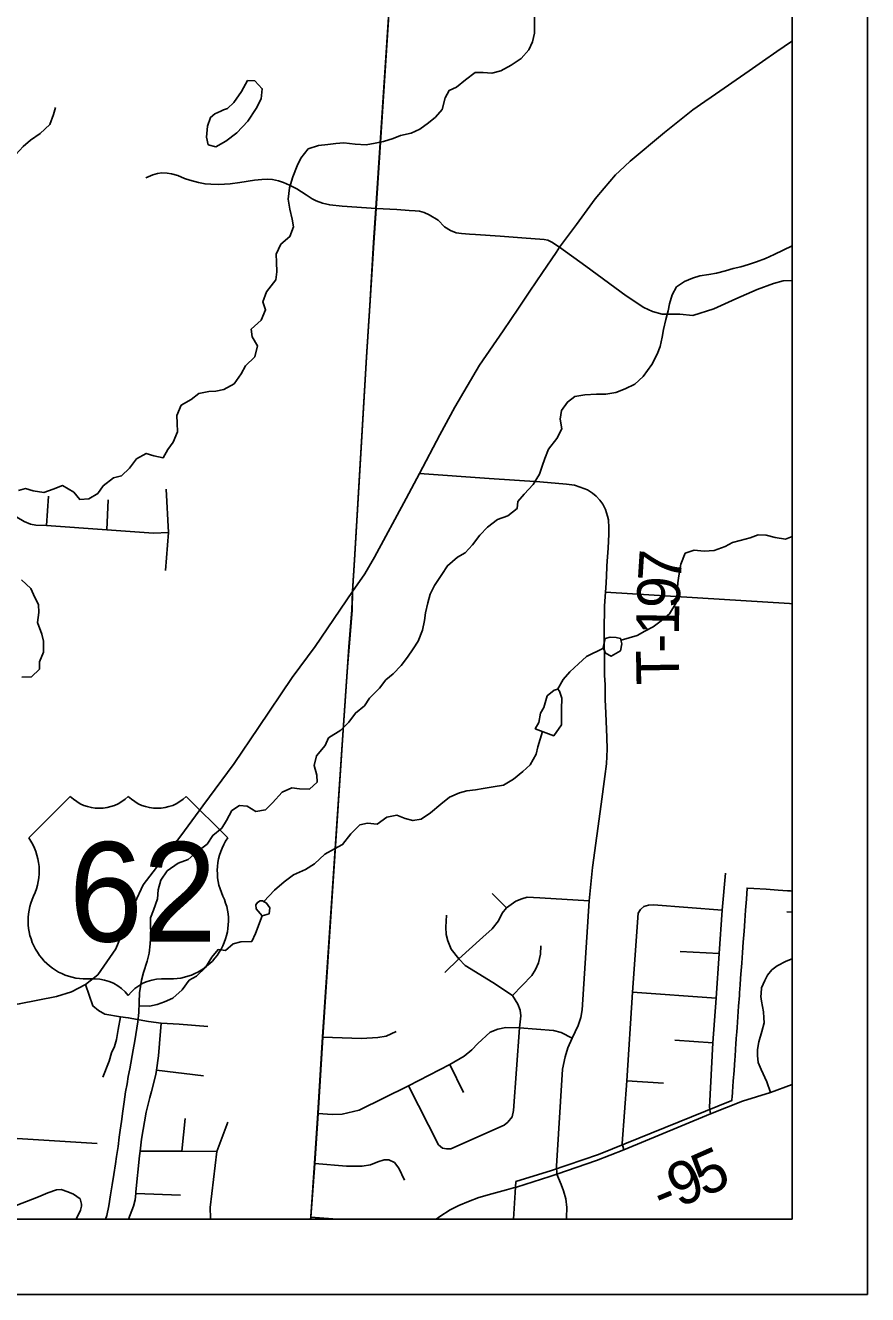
# Model space of a CAD drawing. Extents: x 0 to 34, y 0 to 22.
# Drawn here: x 7.884 to 9, y 14 to 15.681 of the extents above; entities that cross this region are included whole.
import ezdxf

# ---------------------------------------------------------------- set-up
doc = ezdxf.new("R2010")
doc.units = 0
for name, color, linetype in [('GM_X_City_Street', 7, 'Continuous'), ('GM_X_Corporation', 7, 'Continuous'), ('GM_X_County_Road', 7, 'Continuous'), ('GM_X_County_Road_Text', 7, 'Continuous'), ('GM_X_Minor_Lake', 7, 'Continuous'), ('GM_X_Minor_River', 7, 'Continuous'), ('GM_X_Township_Road', 7, 'Continuous'), ('GM_X_Township_Road_Text', 7, 'Continuous'), ('GM_X_US_Location', 7, 'Continuous'), ('GM_X_US_Route', 7, 'Continuous'), ('GM_X_US_Shield', 7, 'Continuous'), ('SH_Data', 7, 'Continuous')]:
    doc.layers.add(name, color=color, linetype=linetype)

msp = doc.modelspace()

# ---------------------------------------------------------------- linework, layer by layer
at = {"layer": 'GM_X_City_Street'}
for p, q in [((7.9123, 15.0186), (7.9148, 15.0576)), ((7.9922, 15.013), (7.994, 15.0525)), ((8.5026, 14.5312), (8.5215, 14.5123)), ((8.4398, 14.4266), (8.4584, 14.4448)), ((8.7518, 14.4545), (8.8034, 14.4519)), ((8.6883, 14.4006), (8.7994, 14.3925)), ((8.7445, 14.3368), (8.7951, 14.3337)), ((8.0579, 14.2972), (8.12, 14.2897)), ((8.4647, 14.2675), (8.4465, 14.3047)), ((8.681, 14.2831), (8.7295, 14.28)), ((8.0916, 14.19), (8.0957, 14.2332)), ((8.1376, 14.1897), (8.1524, 14.2283)), ((8.0303, 14.1339), (8.0896, 14.1318)), ((8.2625, 14.1028), (8.2971, 14.1))]:
    msp.add_line(p, q, dxfattribs=at)
for points in [[(8.3274, 15.0917), (8.3363, 15.2416), (8.3407, 15.3098), (8.3456, 15.3931), (8.3487, 15.4386), (8.3661, 15.702)], [(8.0437, 15.4792), (8.0531, 15.4833), (8.0593, 15.485), (8.0649, 15.4858), (8.0718, 15.4855), (8.0777, 15.4846), (8.086, 15.4822), (8.0949, 15.4782), (8.1019, 15.476), (8.1135, 15.4729), (8.1222, 15.4712), (8.1299, 15.4707), (8.1404, 15.4703), (8.1554, 15.4714), (8.1682, 15.473), (8.1875, 15.476), (8.1974, 15.4771), (8.2044, 15.4774), (8.2114, 15.477), (8.2193, 15.4753), (8.2263, 15.473), (8.2341, 15.4696), (8.2436, 15.4645), (8.256, 15.4565), (8.264, 15.4514), (8.2692, 15.4486), (8.2778, 15.4457), (8.2874, 15.4434), (8.3039, 15.4415), (8.3487, 15.4386)], [(8.3487, 15.4386), (8.3762, 15.4371), (8.3926, 15.436), (8.4006, 15.4356), (8.4064, 15.4349), (8.4126, 15.4334), (8.419, 15.4303), (8.4309, 15.423), (8.4393, 15.4145), (8.4473, 15.4093), (8.4547, 15.4065), (8.4619, 15.4054), (8.4725, 15.4044), (8.4805, 15.404), (8.5132, 15.4017), (8.5476, 15.3993), (8.5658, 15.398), (8.5713, 15.3976), (8.5763, 15.3966), (8.5818, 15.3941), (8.592, 15.3872)], [(8.592, 15.3872), (8.6267, 15.362), (8.6799, 15.323), (8.7036, 15.3073), (8.715, 15.3023), (8.7276, 15.2987), (8.7511, 15.2985), (8.7684, 15.2969), (8.7962, 15.3057), (8.8252, 15.3187), (8.8535, 15.3312), (8.8754, 15.3394), (8.8879, 15.3427), (8.9, 15.3431)], [(8.3176, 14.9313), (8.3203, 14.9727), (8.3274, 15.0917)], [(7.7149, 15.0649), (7.8018, 15.0588), (7.8254, 15.0572), (7.8335, 15.0558), (7.84, 15.0528), (7.8479, 15.0482), (7.8728, 15.0297), (7.8825, 15.0239), (7.8911, 15.0204), (7.8982, 15.0192), (7.9123, 15.0186), (7.9922, 15.013), (8.0541, 15.0084), (8.0738, 15.0093)], [(8.0698, 14.959), (8.0738, 15.0093), (8.0708, 15.067)], [(8.2623, 14.1), (8.2625, 14.1028), (8.2675, 14.1737), (8.2719, 14.2398), (8.2782, 14.341), (8.3054, 14.7474), (8.311, 14.8311), (8.313, 14.8575), (8.317, 14.9065), (8.3176, 14.9313)], [(8.6529, 14.9305), (8.8965, 14.9154), (8.9, 14.9151)], [(8.7917, 14.2395), (8.7907, 14.2482), (8.7951, 14.3337), (8.7994, 14.3925), (8.8034, 14.4519), (8.8075, 14.5093), (8.8116, 14.5583)], [(8.4584, 14.4448), (8.4903, 14.4736), (8.5026, 14.4843), (8.5109, 14.4949), (8.516, 14.5052), (8.5215, 14.5123), (8.5338, 14.521), (8.542, 14.5241), (8.5491, 14.5265), (8.5657, 14.5257), (8.6313, 14.5214)], [(8.677, 14.1916), (8.6749, 14.2003), (8.681, 14.2831), (8.6883, 14.4006), (8.696, 14.5054), (8.6993, 14.5101), (8.7035, 14.5141), (8.7098, 14.516), (8.7165, 14.5164), (8.8075, 14.5093)], [(8.3916, 14.2767), (8.4315, 14.1985), (8.4366, 14.1941), (8.4422, 14.1933), (8.4477, 14.1929), (8.5184, 14.2245), (8.5235, 14.2285), (8.529, 14.2356), (8.531, 14.2439), (8.5389, 14.3532), (8.5405, 14.3694), (8.5397, 14.3769), (8.5365, 14.3848), (8.5294, 14.3962), (8.5034, 14.4132), (8.467, 14.4357), (8.4584, 14.4448), (8.4481, 14.4574), (8.4438, 14.4685), (8.4418, 14.4771), (8.4414, 14.4866), (8.4422, 14.5024)], [(8.5294, 14.3962), (8.5551, 14.4227), (8.5602, 14.4306), (8.5641, 14.4393), (8.5665, 14.4511), (8.5669, 14.4618)], [(7.9636, 14.4109), (7.9736, 14.3823), (7.9811, 14.3761), (7.9893, 14.3714), (8.0104, 14.3678), (8.0204, 14.3668), (8.0472, 14.3619), (8.0641, 14.3597), (8.0881, 14.3583), (8.1259, 14.3552)], [(7.9866, 14.2881), (7.9952, 14.3092), (7.9981, 14.3202), (8.0024, 14.3288), (8.0051, 14.3379), (8.0069, 14.3511), (8.0104, 14.3678)], [(8.0209, 14.1), (8.0272, 14.1171), (8.0296, 14.1254), (8.0303, 14.1339), (8.0305, 14.136), (8.0354, 14.1837), (8.0362, 14.1902), (8.038, 14.206), (8.0442, 14.2415), (8.0491, 14.2612), (8.0511, 14.2691), (8.0571, 14.2917), (8.0579, 14.2972), (8.0605, 14.3163), (8.0619, 14.3326), (8.0641, 14.3597)], [(8.2719, 14.2398), (8.2908, 14.2386), (8.304, 14.2392), (8.3264, 14.2445), (8.3916, 14.2767), (8.4465, 14.3047), (8.4655, 14.3157), (8.4757, 14.3244), (8.4836, 14.3327), (8.4998, 14.3477), (8.5101, 14.3516), (8.5207, 14.3536), (8.5389, 14.3532), (8.5839, 14.3497), (8.5938, 14.3473), (8.6084, 14.3398)], [(8.2782, 14.341), (8.3293, 14.3394), (8.3513, 14.3406), (8.3623, 14.3425), (8.3756, 14.3485)], [(7.8315, 14.2092), (7.8735, 14.2066), (7.9792, 14.2)], [(8.0362, 14.1902), (8.0916, 14.19), (8.1376, 14.1897)], [(8.1294, 14.1), (8.1294, 14.1012), (8.1291, 14.1152), (8.1376, 14.1897)], [(8.2675, 14.1737), (8.3097, 14.1702), (8.3305, 14.1702), (8.3412, 14.1718), (8.351, 14.1759), (8.3595, 14.1787), (8.3658, 14.1784), (8.3731, 14.1749), (8.379, 14.1677), (8.3866, 14.1516)], [(7.6779, 14.1245), (7.7474, 14.1256), (7.7764, 14.1231), (7.8273, 14.1152), (7.8366, 14.1138), (7.8536, 14.1144), (7.8699, 14.1169), (7.8743, 14.1187), (7.8855, 14.1235), (7.9015, 14.1294), (7.914, 14.135), (7.9254, 14.1387), (7.9315, 14.1394), (7.9402, 14.1363), (7.9481, 14.1332), (7.9568, 14.1267)], [(7.9515, 14.1), (7.9515, 14.1), (7.9574, 14.1117), (7.9586, 14.117), (7.9583, 14.1196), (7.9568, 14.1267)]]:
    msp.add_lwpolyline(points, dxfattribs=at)
at = {"layer": 'GM_X_Corporation'}
msp.add_lwpolyline([(6.2393, 14.1), (8.5308, 14.1), (8.5331, 14.1354), (8.534, 14.1497), (8.5814, 14.1642), (8.6433, 14.1855), (8.8201, 14.257), (8.8202, 14.2591), (8.8204, 14.2611), (8.8209, 14.2686), (8.8219, 14.2827), (8.823, 14.297), (8.824, 14.3114), (8.8243, 14.3151), (8.825, 14.3255), (8.8255, 14.3319), (8.826, 14.3393), (8.8267, 14.3482), (8.8271, 14.3539), (8.8276, 14.3609), (8.8281, 14.368), (8.8291, 14.3819), (8.8301, 14.396), (8.8304, 14.3997), (8.8312, 14.4105), (8.8318, 14.4187), (8.8322, 14.4246), (8.8329, 14.4343), (8.8332, 14.4389), (8.8342, 14.4531), (8.8352, 14.467), (8.8363, 14.4813), (8.8373, 14.4951), (8.8383, 14.5091), (8.8394, 14.5237), (8.8404, 14.5385), (8.8493, 14.5379), (8.8654, 14.5368), (8.8813, 14.5357), (8.8937, 14.5349), (8.898, 14.5346), (8.9, 14.5345), (8.9, 16.0691)], dxfattribs=at)
at = {"layer": 'GM_X_County_Road'}
msp.add_line((8.5214, 14.1387), (8.5309, 14.1414), dxfattribs=at)
for points in [[(3.5033, 14.1), (8.2619, 14.1), (8.2622, 14.1033), (8.2673, 14.1742), (8.2717, 14.2404), (8.278, 14.3415), (8.3052, 14.7479), (8.3108, 14.8316), (8.3128, 14.8581), (8.3168, 14.9071), (8.3174, 14.9318), (8.3201, 14.9732), (8.3361, 15.2422), (8.3405, 15.3103), (8.3454, 15.3937), (8.3484, 15.4392), (8.3775, 15.8788), (8.3884, 16.1033), (8.0841, 16.1202), (7.7224, 16.142)], [(8.5788, 14.1566), (8.5884, 14.1597), (8.6406, 14.1775), (8.677, 14.1916), (8.7526, 14.2231), (8.7917, 14.2395), (8.8341, 14.2563), (8.8714, 14.2679), (8.9, 14.2785)], [(8.5309, 14.1414), (8.5348, 14.1425), (8.5788, 14.1566)], [(8.4286, 14.1), (8.4334, 14.1035), (8.4471, 14.1122), (8.4584, 14.1179), (8.4714, 14.1233), (8.4851, 14.1285), (8.5023, 14.1334), (8.5214, 14.1387)]]:
    msp.add_lwpolyline(points, dxfattribs=at)
msp.add_lwpolyline([(8.2619, 14.1), (8.9, 14.1), (8.9, 16.069), (8.5217, 16.0919), (8.4715, 16.0965), (8.3884, 16.1033), (8.3775, 15.8788), (8.3484, 15.4392), (8.3454, 15.3937), (8.3405, 15.3103), (8.3361, 15.2422), (8.3201, 14.9732), (8.3174, 14.9318), (8.3168, 14.9071), (8.3128, 14.8581), (8.3108, 14.8316), (8.3052, 14.7479), (8.278, 14.3415), (8.2717, 14.2404), (8.2673, 14.1742), (8.2622, 14.1033)], close=True, dxfattribs=at)
at = {"layer": 'GM_X_Minor_Lake'}
for points in [[(8.1351, 15.5641), (8.1294, 15.5592), (8.1255, 15.5478), (8.1243, 15.533), (8.1265, 15.5231), (8.1367, 15.5201), (8.1496, 15.5276), (8.1641, 15.5389), (8.1787, 15.5543), (8.1898, 15.571), (8.1967, 15.5838), (8.1979, 15.5971), (8.1881, 15.6078), (8.1786, 15.6079), (8.1706, 15.5935), (8.1602, 15.5791), (8.1518, 15.5708)], [(7.7949, 15.4836), (7.8089, 15.478), (7.8226, 15.4832), (7.837, 15.4865), (7.8473, 15.4906), (7.8584, 15.4963), (7.8717, 15.5102), (7.8813, 15.5208), (7.8908, 15.5291), (7.9038, 15.5381), (7.9164, 15.5498), (7.9214, 15.5631), (7.9241, 15.5725)], [(8.1518, 15.5708), (8.1468, 15.5692), (8.1431, 15.5676), (8.1351, 15.5641)], [(8.6498, 14.8571), (8.6528, 14.8498), (8.6604, 14.8456), (8.6726, 14.8528), (8.6745, 14.8619), (8.6727, 14.8691), (8.667, 14.8703), (8.6587, 14.8707), (8.6522, 14.869)], [(8.6522, 14.869), (8.6498, 14.8571)], [(8.5846, 14.8005), (8.5754, 14.793), (8.5712, 14.7778), (8.5666, 14.7703), (8.5642, 14.7578), (8.5596, 14.7495), (8.5842, 14.7402), (8.5945, 14.7546), (8.5943, 14.7754), (8.5948, 14.7902), (8.5918, 14.7994)], [(8.5918, 14.7994), (8.5895, 14.8017), (8.5846, 14.8005)], [(8.1979, 14.5015), (8.207, 14.5045), (8.2082, 14.5125), (8.2037, 14.5186), (8.1984, 14.5216), (8.1953, 14.5216), (8.1915, 14.5194), (8.1896, 14.5164), (8.19, 14.511)], [(8.19, 14.511), (8.1979, 14.5015)]]:
    msp.add_lwpolyline(points, dxfattribs=at)
at = {"layer": 'GM_X_Minor_River'}
for points in [[(8.3588, 15.5271), (8.3713, 15.5312), (8.3812, 15.5353), (8.3953, 15.5383), (8.4067, 15.5435), (8.4181, 15.5522), (8.4277, 15.5597), (8.4365, 15.5695), (8.4403, 15.5851), (8.4457, 15.5949), (8.4552, 15.5994), (8.4671, 15.6092), (8.48, 15.6186), (8.4907, 15.6189), (8.502, 15.6177), (8.5142, 15.6207), (8.5279, 15.6282), (8.5409, 15.6372), (8.5512, 15.6489), (8.5562, 15.6595), (8.5585, 15.6709), (8.5587, 15.6978)], [(7.875, 15.0651), (7.8845, 15.0677), (7.8947, 15.0646), (7.9084, 15.0626), (7.9209, 15.0667), (7.9335, 15.0715), (7.9482, 15.0627), (7.9561, 15.0532), (7.9683, 15.0539), (7.9801, 15.061), (7.987, 15.0712), (8.0011, 15.0818), (8.0114, 15.0844), (8.0221, 15.0945), (8.0316, 15.107), (8.0442, 15.1142), (8.0544, 15.1111), (8.0666, 15.1083), (8.0731, 15.1193), (8.08, 15.1291), (8.0857, 15.1427), (8.0851, 15.1541), (8.0847, 15.1644), (8.0905, 15.178), (8.1039, 15.1855), (8.1138, 15.1934), (8.1271, 15.196), (8.1366, 15.1967), (8.1472, 15.1989), (8.1609, 15.2064), (8.1701, 15.2197), (8.1759, 15.2303), (8.1881, 15.2423), (8.1916, 15.2567), (8.1845, 15.2685), (8.1834, 15.2788), (8.1967, 15.2905), (8.2025, 15.3045), (8.1988, 15.3151), (8.2038, 15.3284), (8.2161, 15.3443), (8.2173, 15.3545), (8.217, 15.3674), (8.2163, 15.378), (8.2224, 15.3913), (8.2346, 15.4014), (8.2396, 15.4143), (8.2378, 15.4246), (8.2345, 15.4375), (8.2323, 15.4508), (8.2339, 15.466), (8.2385, 15.4804), (8.2443, 15.4951), (8.2489, 15.5053), (8.2589, 15.5174), (8.2726, 15.5219), (8.2847, 15.5234), (8.2954, 15.5248), (8.306, 15.5255), (8.3212, 15.5239), (8.3356, 15.5227), (8.3474, 15.5249), (8.3588, 15.5271)], [(8.0599, 14.5361), (8.0638, 14.549), (8.0722, 14.5615), (8.0864, 14.5716), (8.1, 14.5761), (8.1115, 14.5866), (8.1248, 14.5968), (8.1325, 14.6082), (8.1443, 14.618), (8.1508, 14.6278), (8.1578, 14.641), (8.1677, 14.6478), (8.1779, 14.647), (8.1896, 14.6401), (8.2022, 14.6419), (8.2117, 14.6513), (8.2243, 14.6653), (8.2373, 14.6713), (8.2475, 14.6697), (8.2604, 14.6693), (8.2707, 14.6787), (8.2704, 14.6882), (8.2667, 14.7007), (8.2698, 14.7136), (8.2813, 14.7272), (8.2859, 14.7374), (8.3019, 14.7476), (8.3126, 14.7581), (8.3214, 14.7702), (8.3336, 14.78), (8.3401, 14.7898), (8.3531, 14.8034), (8.3619, 14.8144), (8.3714, 14.8223), (8.3821, 14.8332), (8.3902, 14.8442), (8.3978, 14.8555), (8.4047, 14.8654), (8.4105, 14.8801), (8.4129, 14.893), (8.4144, 14.9032), (8.4172, 14.9161), (8.4203, 14.9279), (8.4264, 14.9392), (8.436, 14.954), (8.4433, 14.9653), (8.4566, 14.9766), (8.4666, 14.9823), (8.4765, 14.9932), (8.4861, 15.0057), (8.4964, 15.0166), (8.5097, 15.0268), (8.5234, 15.0316), (8.5356, 15.041), (8.5364, 15.0505), (8.5448, 15.0603), (8.5567, 15.0728), (8.5651, 15.0868), (8.569, 15.0974), (8.5725, 15.1076), (8.5771, 15.1197), (8.5882, 15.1341), (8.5947, 15.1466), (8.5925, 15.1595), (8.5945, 15.1712), (8.6022, 15.1822), (8.6121, 15.1897), (8.6254, 15.1919), (8.6409, 15.1926), (8.6531, 15.1925), (8.6664, 15.1947), (8.6789, 15.1996), (8.6915, 15.206), (8.7026, 15.2161), (8.7141, 15.232), (8.7213, 15.2456), (8.7252, 15.2559), (8.7276, 15.268), (8.7295, 15.2782), (8.7326, 15.2915), (8.7357, 15.3029), (8.7377, 15.3123), (8.7412, 15.3241), (8.747, 15.3347), (8.7572, 15.3418), (8.7679, 15.3463), (8.7778, 15.3493), (8.7896, 15.3511), (8.7998, 15.3529), (8.8116, 15.3559), (8.8219, 15.3589), (8.8321, 15.3615), (8.8424, 15.3645), (8.8527, 15.3678), (8.8648, 15.3723), (8.8763, 15.3775), (8.9, 15.3892)], [(8.6733, 14.8666), (8.6947, 14.8731), (8.705, 14.8788), (8.7157, 14.8844), (8.7263, 14.8923), (8.7374, 14.9017), (8.7462, 14.9161), (8.7478, 14.9294), (8.7487, 14.9426), (8.7499, 14.9521), (8.7526, 14.9677), (8.7584, 14.982), (8.7702, 14.9862), (8.7835, 14.9846), (8.7968, 14.9856), (8.8112, 14.9908), (8.8211, 14.9961), (8.831, 14.9987), (8.8443, 15.0024), (8.855, 15.0065), (8.8656, 15.0057), (8.8773, 15.003), (8.8914, 15.0006), (8.9, 15.0042)], [(7.8795, 14.818), (7.8924, 14.8183), (7.9027, 14.8285), (7.9028, 14.838), (7.9082, 14.8508), (7.9083, 14.8653), (7.9061, 14.8747), (7.9001, 14.89), (7.9021, 14.9036), (7.9014, 14.9139), (7.8969, 14.9234), (7.8913, 14.9352), (7.8792, 14.9466)], [(8.5892, 14.8016), (8.5968, 14.8149), (8.6056, 14.8247), (8.6171, 14.8356), (8.6274, 14.8454), (8.6502, 14.8562)], [(8.2, 14.5207), (8.214, 14.5356), (8.227, 14.5469), (8.2396, 14.5559), (8.2552, 14.563), (8.2674, 14.5705), (8.2807, 14.5834), (8.2937, 14.5905), (8.3044, 14.5961), (8.3154, 14.6101), (8.3273, 14.6222), (8.3372, 14.6244), (8.3504, 14.6232), (8.363, 14.6322), (8.3763, 14.6352), (8.3873, 14.6306), (8.3975, 14.6278), (8.4086, 14.6297), (8.4211, 14.6383), (8.4345, 14.6496), (8.4459, 14.6587), (8.4593, 14.6647), (8.4688, 14.6673), (8.4805, 14.6687), (8.4908, 14.6702), (8.5041, 14.6724), (8.5178, 14.6746), (8.5307, 14.6825), (8.5433, 14.693), (8.5528, 14.7017), (8.5609, 14.7157), (8.5629, 14.7255), (8.5692, 14.7458)], [(7.9904, 14.1), (7.992, 14.105), (7.9947, 14.1175), (7.9971, 14.1323), (7.9991, 14.1456), (8.0014, 14.1592), (8.0034, 14.1733), (8.005, 14.1828), (8.007, 14.196), (8.0086, 14.2085), (8.0098, 14.218), (8.0113, 14.2294), (8.0133, 14.243), (8.0149, 14.2552), (8.0169, 14.2684), (8.0189, 14.2794), (8.0204, 14.2889), (8.0224, 14.2991), (8.0271, 14.3242), (8.0291, 14.3363), (8.033, 14.3613), (8.0343, 14.3735), (8.0351, 14.3871), (8.0352, 14.3996), (8.0379, 14.4163), (8.0407, 14.4265), (8.0453, 14.4417), (8.048, 14.4523), (8.0496, 14.4648), (8.0505, 14.4789), (8.0498, 14.4887), (8.0498, 14.499), (8.0541, 14.5092), (8.0591, 14.5243), (8.0599, 14.5361)], [(8.0348, 14.3827), (8.0484, 14.3821), (8.0586, 14.3843), (8.0685, 14.3877), (8.0795, 14.3925), (8.0921, 14.4035), (8.1013, 14.4167), (8.1108, 14.4216), (8.1227, 14.4333), (8.1311, 14.4469), (8.1395, 14.4571), (8.1494, 14.4559), (8.1593, 14.4646), (8.1696, 14.4671), (8.184, 14.4678), (8.189, 14.4784), (8.1979, 14.5015)]]:
    msp.add_lwpolyline(points, dxfattribs=at)
at = {"layer": 'GM_X_Township_Road'}
for p, q in [((8.6554, 14.977), (8.6561, 14.9886)), ((8.6546, 14.9654), (8.6554, 14.977)), ((8.893, 14.507), (8.9, 14.5065)), ((8.601, 14.1), (8.601, 14.102))]:
    msp.add_line(p, q, dxfattribs=at)
for points in [[(8.6569, 15.0229), (8.6568, 15.026), (8.6556, 15.0311), (8.6527, 15.0399), (8.6493, 15.0468), (8.6452, 15.0524), (8.6404, 15.0577), (8.6356, 15.0614), (8.6287, 15.0658), (8.6193, 15.0696), (8.6117, 15.0719), (8.6009, 15.0736), (8.5657, 15.0765), (8.4985, 15.0808), (8.4065, 15.0877)], [(8.6561, 14.9886), (8.6573, 15.0072), (8.6572, 15.0188), (8.6569, 15.0229)], [(8.6535, 14.9421), (8.6545, 14.9631), (8.6546, 14.9654)], [(8.6516, 14.9104), (8.6516, 14.9124), (8.6529, 14.9305), (8.6535, 14.9421)], [(8.6516, 14.8202), (8.6512, 14.8282), (8.651, 14.8801), (8.6516, 14.9104)], [(8.6531, 14.7701), (8.6523, 14.7881), (8.6522, 14.8082), (8.6516, 14.8202)], [(8.588, 14.17), (8.5957, 14.2987), (8.5992, 14.3151), (8.6029, 14.327), (8.6084, 14.3398), (8.6165, 14.3566), (8.6201, 14.3671), (8.6218, 14.3773), (8.6313, 14.5214), (8.6353, 14.5656), (8.6469, 14.6498), (8.652, 14.6864), (8.6542, 14.7031), (8.6548, 14.7223), (8.6546, 14.7381), (8.6531, 14.7701)], [(8.8714, 14.2679), (8.8663, 14.282), (8.8588, 14.2981), (8.8551, 14.3076), (8.8539, 14.3167), (8.8541, 14.3246), (8.8559, 14.3347), (8.86, 14.3485), (8.8628, 14.3599), (8.8624, 14.3668), (8.862, 14.3747), (8.8592, 14.3887), (8.8584, 14.3947), (8.8588, 14.399), (8.8594, 14.4065), (8.8637, 14.4162), (8.8673, 14.4229), (8.8732, 14.43), (8.8803, 14.4355), (8.8922, 14.4416), (8.9, 14.4448)], [(8.601, 14.102), (8.6015, 14.1153), (8.6002, 14.1269), (8.5972, 14.1376), (8.594, 14.146), (8.5884, 14.1597), (8.588, 14.17)]]:
    msp.add_lwpolyline(points, dxfattribs=at)
at = {"layer": 'GM_X_US_Route'}
msp.add_line((8.8993, 15.6597), (8.9, 15.6602), dxfattribs=at)
for points in [[(8.8606, 15.6333), (8.8798, 15.6467), (8.8993, 15.6597)], [(8.6714, 15.4881), (8.6856, 15.5012), (8.731, 15.5391), (8.7684, 15.5691), (8.7843, 15.5802), (8.7927, 15.586), (8.843, 15.621), (8.8606, 15.6333)], [(8.651, 15.4653), (8.6662, 15.4833), (8.6714, 15.4881)], [(8.4065, 15.0877), (8.4334, 15.1387), (8.4531, 15.1753), (8.486, 15.2309), (8.517, 15.2764), (8.5374, 15.3066), (8.5525, 15.329), (8.5693, 15.3539), (8.5872, 15.3805), (8.592, 15.3872), (8.6143, 15.4175), (8.6391, 15.4512), (8.651, 15.4653)], [(7.7755, 14.3616), (7.7941, 14.3707), (7.8501, 14.381), (7.876, 14.385), (7.9256, 14.3947), (7.9454, 14.4011), (7.9636, 14.4109), (7.9802, 14.4236), (8.0039, 14.458), (8.0292, 14.5189), (8.0402, 14.5426), (8.0903, 14.6078), (8.1192, 14.6475), (8.1609, 14.7034), (8.1929, 14.751), (8.2377, 14.8175), (8.2679, 14.8583), (8.3176, 14.9313), (8.3341, 14.9548), (8.3466, 14.9768), (8.3885, 15.0545), (8.4065, 15.0877)]]:
    msp.add_lwpolyline(points, dxfattribs=at)
at = {"layer": 'GM_X_US_Shield'}
for p, q in [((7.9436, 14.6598), (7.8886, 14.6049)), ((8.1523, 14.6049), (8.0974, 14.6598)), ((7.9655, 14.4181), (7.9765, 14.4181)), ((8.0644, 14.4181), (8.0754, 14.4181))]:
    msp.add_line(p, q, dxfattribs=at)
for centre, radius, start, end in [((7.982, 14.699), 0.0549, 225.573, 314.427), ((8.0589, 14.699), 0.0549, 225.573, 314.427), ((7.8256, 14.5608), 0.0769, 334.5471, 35.0009), ((8.2153, 14.5608), 0.0769, 144.9991, 205.4529), ((7.9647, 14.495), 0.0769, 154.8319, 270.6383), ((8.0763, 14.495), 0.0769, 269.3617, 25.1681), ((7.9765, 14.3632), 0.0549, 36.8699, 90), ((8.0644, 14.3632), 0.0549, 90, 143.1301)]:
    msp.add_arc(centre, radius, start, end, dxfattribs=at)
at = {"layer": 'SH_Data'}
for p, q in [((9, 21), (9, 14)), ((8.9, 20.9), (8.9, 14.1)), ((2.1, 14.1), (8.9, 14.1)), ((2, 14), (9, 14))]:
    msp.add_line(p, q, dxfattribs=at)

# ---------------------------------------------------------------- texts
at = {"layer": 'GM_X_County_Road_Text'}
for s, rotation, p in [('5', 23.7232, (8.7831, 14.1289)), ('9', 22.6052, (8.7496, 14.115)), ('-', 22.3465, (8.7278, 14.106))]:
    msp.add_text(s, height=0.0568, rotation=rotation, dxfattribs=at).set_placement(p)
at = {"layer": 'GM_X_Township_Road_Text'}
for s, rotation, p in [('7', 86.3496, (8.7522, 14.9424)), ('9', 87.1313, (8.7505, 14.9077)), ('1', 89.0737, (8.7499, 14.8732)), ('-', 90.0234, (8.7499, 14.8501)), ('T', 91.0372, (8.7507, 14.8079))]:
    msp.add_text(s, height=0.0568, rotation=rotation, dxfattribs=at).set_placement(p)
at = {"layer": 'GM_X_US_Location'}
for s in ['0', '/']:
    msp.add_text(s, height=0.000189, dxfattribs=at).set_placement((8.0204, 14.5324))
msp.add_text('62', height=0.000189, rotation=0, dxfattribs=at).set_placement((7.9813, 14.4932))
at = {"layer": 'GM_X_US_Shield'}
msp.add_text('62', height=0.13184, dxfattribs=at).set_placement((7.9417, 14.4676))

doc.saveas('drawing.dxf')
